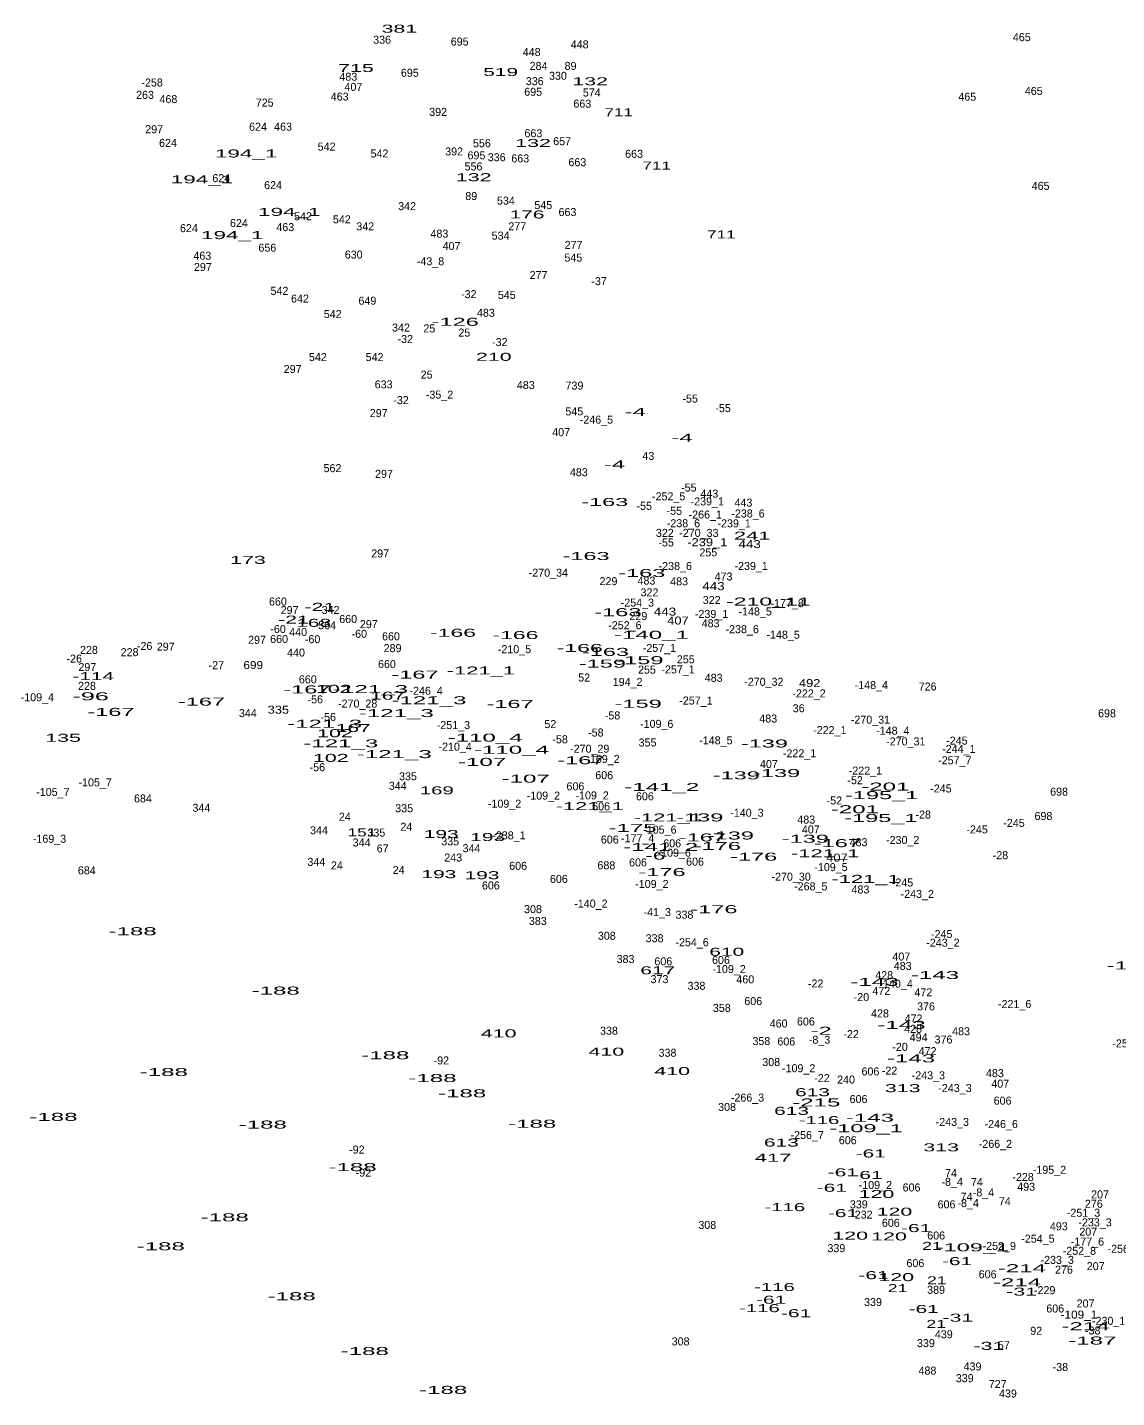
# Model space of a CAD drawing. Extents: x -658595 to -655205, y -1004347 to -1000147.
# Drawn here: x -656433 to -655888, y -1002919 to -1002234 of the extents above; entities that cross this region are included whole.
import ezdxf
from ezdxf.enums import TextEntityAlignment as Align

# ---------------------------------------------------------------- set-up
doc = ezdxf.new("R2010")
doc.units = 0
doc.header["$LTSCALE"] = 1.6
doc.layers.add('24', color=7, linetype='Continuous')

msp = doc.modelspace()

# ---------------------------------------------------------------- texts
at = {"layer": '24'}
for s, width, p in [('381', 2, (-656246.827, -1002236.84)), ('715', 2, (-656268.523, -1002256.5)), ('519', 1.95, (-656196.223, -1002258.51)), ('132', 2, (-656151.497, -1002263.15)), ('711', 1.6, (-656137.239, -1002278.62)), ('194_1', 2.1, (-656323.435, -1002299.23)), ('132', 2, (-656180.027, -1002293.97)), ('711', 1.6, (-656118.229, -1002305.26)), ('194_1', 2.1, (-656345.495, -1002312.17)), ('132', 2, (-656209.697, -1002311.09)), ('194_1', 2.1, (-656301.855, -1002328.43)), ('176', 1.95, (-656183.047, -1002329.73)), ('194_1', 2.1, (-656330.385, -1002340.03)), ('711', 1.6, (-656085.899, -1002339.69)), ('-126', 2.2, (-656218.915, -1002383.38)), ('210', 2, (-656199.664, -1002400.89)), ('-4', 2.25, (-656128.98, -1002428.43)), ('-4', 2.25, (-656105.59, -1002441.37)), ('-4', 2.25, (-656139.34, -1002454.68)), ('-163', 2.2, (-656144.225, -1002473.46)), ('241', 2.05, (-656070.523, -1002490.27)), ('-239_1', 1.2, (-656092.931, -1002493.55)), ('443', 1.25, (-656071.79, -1002494.51)), ('173', 2, (-656322.523, -1002502.4)), ('-163', 2.2, (-656153.545, -1002500.48)), ('-163', 2.2, (-656125.685, -1002508.95)), ('443', 1.25, (-656089.85, -1002515.51)), ('-210_11', 2.15, (-656062.46, -1002523.24)), ('-21', 2, (-656299.771, -1002532.26)), ('-21', 2, (-656286.561, -1002525.88)), ('-163', 2.2, (-656137.665, -1002528.54)), ('443', 1.25, (-656114.1, -1002528.25)), ('168', 1.95, (-656289.653, -1002533.87)), ('-166', 2.15, (-656220.039, -1002538.84)), ('407', 1.2, (-656107.61, -1002532.72)), ('-166', 2.15, (-656188.849, -1002539.98)), ('-140_1', 2.25, (-656120.869, -1002539.85)), ('-166', 2.15, (-656156.709, -1002546.45)), ('-163', 2.2, (-656143.845, -1002548.41)), ('-159', 2.2, (-656126.635, -1002552.54)), ('699', 1.1, (-656319.89, -1002554.98)), ('-121_1', 2.05, (-656206.134, -1002557.7)), ('-159', 2.2, (-656145.375, -1002554.26)), ('-114', 1.95, (-656399.862, -1002560.53)), ('-167', 2.2, (-656239.059, -1002559.75)), ('492', 1.2, (-656041.78, -1002563.99)), ('-96', 2.35, (-656401.153, -1002570.6)), ('-167', 2.2, (-656345.749, -1002573.25)), ('-167', 2.2, (-656293.069, -1002567.17)), ('102', 2, (-656279.644, -1002566.87)), ('-121_3', 2.25, (-656261.247, -1002567)), ('167', 1.95, (-656252.737, -1002570.28)), ('-121_3', 2.25, (-656232.067, -1002572.58)), ('-167', 2.2, (-656391.009, -1002578.39)), ('335', 1.2, (-656307.34, -1002577.29)), ('-121_3', 2.25, (-656248.357, -1002578.98)), ('-167', 2.2, (-656191.509, -1002574.4)), ('-159', 2.2, (-656127.485, -1002574.32)), ('-121_3', 2.25, (-656284.207, -1002584.3)), ('167', 1.95, (-656269.877, -1002586.43)), ('135', 2, (-656414.917, -1002591.35)), ('102', 2, (-656279.044, -1002589.04)), ('-110_4', 2.25, (-656203.979, -1002591.26)), ('-121_3', 2.25, (-656276.137, -1002594.11)), ('-121_3', 2.25, (-656249.367, -1002599.5)), ('-110_4', 2.25, (-656190.819, -1002597.31)), ('-139', 2.2, (-656064.425, -1002594.19)), ('102', 2, (-656281.144, -1002601.4)), ('-107', 2.25, (-656205.501, -1002603.4)), ('-167', 2.2, (-656156.139, -1002602.55)), ('-107', 2.25, (-656183.711, -1002611.76)), ('-139', 2.2, (-656078.455, -1002610.12)), ('-139', 2.2, (-656058.295, -1002608.97)), ('169', 1.9, (-656228.147, -1002617.62)), ('-141_2', 2.25, (-656115.693, -1002615.95)), ('-195_1', 2.2, (-656005.813, -1002620.01)), ('-201', 2.25, (-656003.957, -1002615.73)), ('-121_1', 2.05, (-656151.714, -1002625.5)), ('-201', 2.25, (-656019.167, -1002627.05)), ('-121_1', 2.05, (-656112.684, -1002631.17)), ('-139', 2.2, (-656096.705, -1002631.15)), ('-195_1', 2.2, (-656006.193, -1002631.43)), ('151', 1.6, (-656265.564, -1002638.61)), ('193', 1.95, (-656225.933, -1002639.44)), ('193', 1.95, (-656202.733, -1002640.96)), ('-175', 2.25, (-656130.315, -1002636.42)), ('-167', 2.2, (-656095.429, -1002641.15)), ('-139', 2.2, (-656081.405, -1002640.18)), ('-139', 2.2, (-656043.945, -1002641.8)), ('-141_2', 2.25, (-656116.273, -1002645.92)), ('-176', 2.2, (-656087.929, -1002645.44)), ('-167', 2.2, (-656027.919, -1002644.01)), ('-6', 2.1, (-656118.929, -1002650.25)), ('-176', 2.2, (-656069.769, -1002650.77)), ('-121_1', 2.05, (-656034.034, -1002649.08)), ('407', 1.2, (-656028.13, -1002651.24)), ('193', 1.95, (-656227.123, -1002659.51)), ('193', 1.95, (-656205.533, -1002660.03)), ('-176', 2.2, (-656115.599, -1002658.47)), ('-121_1', 2.05, (-656013.844, -1002661.87)), ('-176', 2.2, (-656089.639, -1002677.02)), ('-188', 2.25, (-656380.171, -1002688.04)), ('610', 1.95, (-656083.229, -1002698.31)), ('617', 1.95, (-656117.717, -1002707.6)), ('-143', 2.25, (-655979.146, -1002709.93)), ('-105_1', 2.25, (-655874.674, -1002705.17)), ('-143', 2.25, (-656009.386, -1002713.35)), ('-188', 2.25, (-656308.661, -1002717.72)), ('-143', 2.25, (-655995.886, -1002734.85)), ('410', 2, (-656197.219, -1002739.11)), ('-2', 2.2, (-656036.024, -1002737.79)), ('-188', 2.25, (-656253.881, -1002750.03)), ('410', 2, (-656143.399, -1002748.24)), ('410', 2, (-656110.499, -1002757.94)), ('-143', 2.25, (-655991.126, -1002751.59)), ('-188', 2.25, (-656364.571, -1002758.43)), ('-188', 2.25, (-656230.301, -1002761.44)), ('-188', 2.25, (-656215.471, -1002769.05)), ('613', 1.95, (-656040.363, -1002768.51)), ('313', 2, (-655995.287, -1002766.49)), ('613', 1.95, (-656050.833, -1002777.83)), ('-215', 2.25, (-656038.461, -1002773.65)), ('-188', 2.25, (-656419.731, -1002780.84)), ('-188', 2.25, (-656315.131, -1002784.69)), ('-188', 2.25, (-656180.471, -1002784.27)), ('-116', 1.9, (-656037.111, -1002782.44)), ('-143', 2.25, (-656011.666, -1002781.27)), ('-109_1', 2.2, (-656013.609, -1002786.52)), ('613', 1.95, (-656055.923, -1002793.67)), ('-61', 1.95, (-656011.255, -1002799.13)), ('313', 2, (-655976.077, -1002796.08)), ('-188', 2.25, (-656270.241, -1002805.96)), ('417', 2.05, (-656060.058, -1002801.28)), ('-61', 1.95, (-656025.225, -1002808.59)), ('-61', 1.95, (-656012.885, -1002809.89)), ('-61', 1.95, (-656030.695, -1002816.28)), ('120', 2, (-656008.404, -1002819.4)), ('-116', 1.9, (-656054.201, -1002825.95)), ('-188', 2.25, (-656334.141, -1002831.07)), ('-61', 1.95, (-656025.125, -1002828.95)), ('120', 2, (-655999.424, -1002828.24)), ('120', 2, (-656021.534, -1002840.22)), ('-61', 1.95, (-655988.555, -1002836.44)), ('-188', 2.25, (-656366.101, -1002845.53)), ('120', 2, (-656002.134, -1002840.61)), ('21', 1.65, (-655980.627, -1002845.34)), ('-109_1', 2.2, (-655960.419, -1002846.07)), ('-61', 1.95, (-655968.105, -1002852.96)), ('-61', 1.95, (-656009.865, -1002859.97)), ('120', 2, (-655998.514, -1002860.96)), ('-214', 2.25, (-655935.676, -1002856.49)), ('-116', 1.9, (-656059.381, -1002865.89)), ('21', 1.65, (-655997.837, -1002866.46)), ('21', 1.65, (-655978.247, -1002862.56)), ('-214', 2.25, (-655938.146, -1002863.53)), ('-188', 2.25, (-656300.671, -1002870.52)), ('-61', 1.95, (-656061.045, -1002872.26)), ('-31', 2, (-655935.841, -1002868.21)), ('-116', 1.9, (-656066.871, -1002876.46)), ('-61', 1.95, (-656048.555, -1002878.99)), ('-61', 1.95, (-655984.805, -1002876.88)), ('-31', 2, (-655967.701, -1002881.24)), ('-109_1', 1.1, (-655907.211, -1002879.69)), ('21', 1.65, (-655978.527, -1002884.34)), ('-214', 2.25, (-655903.906, -1002885.5)), ('-31', 2, (-655952.201, -1002895.32)), ('-187', 2.25, (-655900.515, -1002892.66)), ('-188', 2.25, (-656264.151, -1002897.91)), ('-188', 2.25, (-656224.981, -1002917.32))]:
    msp.add_text(s, height=4, dxfattribs=dict(at, width=width)).set_placement(p, align=Align.CENTER)
for s, p in [('336', (-656255.463, -1002242.35)), ('695', (-656216.688, -1002243.29)), ('465', (-655935.757, -1002241.09)), ('448', (-656180.716, -1002248.52)), ('448', (-656156.746, -1002244.69)), ('284', (-656177.281, -1002255.45)), ('89', (-656161.293, -1002255.45)), ('-258', (-656370.425, -1002263.76)), ('483', (-656272.361, -1002260.85)), ('695', (-656241.618, -1002258.89)), ('336', (-656179.193, -1002263.09)), ('330', (-656167.601, -1002260.39)), ('263', (-656373.983, -1002269.93)), ('463', (-656276.677, -1002270.8)), ('407', (-656269.811, -1002265.94)), ('695', (-656179.988, -1002268.4)), ('574', (-656150.687, -1002268.75)), ('465', (-655963.017, -1002270.86)), ('465', (-655929.797, -1002267.98)), ('468', (-656362.287, -1002272.06)), ('725', (-656314.163, -1002273.8)), ('392', (-656227.483, -1002278.44)), ('663', (-656155.418, -1002274.3)), ('297', (-656369.408, -1002287.1)), ('624', (-656317.507, -1002285.87)), ('463', (-656305.017, -1002285.83)), ('663', (-656179.858, -1002289.14)), ('624', (-656362.497, -1002293.95)), ('542', (-656283.211, -1002295.8)), ('542', (-656256.781, -1002299.23)), ('392', (-656219.493, -1002298.22)), ('556', (-656205.613, -1002294.12)), ('657', (-656165.528, -1002293.1)), ('556', (-656209.803, -1002305.72)), ('695', (-656208.328, -1002300.17)), ('336', (-656198.213, -1002301.11)), ('663', (-656186.418, -1002301.7)), ('663', (-656157.888, -1002303.6)), ('663', (-656129.548, -1002299.41)), ('624', (-656335.867, -1002311.58)), ('624', (-656309.977, -1002315.07)), ('465', (-655926.347, -1002315.42)), ('342', (-656242.991, -1002325.57)), ('89', (-656210.933, -1002320.51)), ('534', (-656193.601, -1002322.79)), ('545', (-656174.921, -1002325.04)), ('542', (-656295.001, -1002330.62)), ('542', (-656275.601, -1002332.14)), ('663', (-656162.838, -1002328.52)), ('624', (-656352.027, -1002336.57)), ('624', (-656327.047, -1002334)), ('463', (-656303.877, -1002336.06)), ('342', (-656263.911, -1002335.66)), ('483', (-656226.851, -1002339.32)), ('534', (-656196.261, -1002340.29)), ('277', (-656187.929, -1002335.62)), ('656', (-656312.828, -1002346.32)), ('407', (-656220.751, -1002345.47)), ('277', (-656159.789, -1002344.95)), ('463', (-656345.337, -1002350.33)), ('630', (-656269.687, -1002349.78)), ('-43_8', (-656231.277, -1002353.12)), ('545', (-656159.901, -1002351.29)), ('297', (-656345.068, -1002355.97)), ('277', (-656177.279, -1002359.98)), ('-37', (-656147.031, -1002363.06)), ('542', (-656306.791, -1002367.9)), ('642', (-656296.547, -1002371.78)), ('649', (-656262.823, -1002372.83)), ('-32', (-656212.155, -1002369.55)), ('545', (-656193.181, -1002369.94)), ('542', (-656280.161, -1002379.51)), ('483', (-656203.611, -1002378.88)), ('342', (-656246.031, -1002386.26)), ('25', (-656231.867, -1002386.68)), ('-32', (-656243.915, -1002392)), ('25', (-656214.377, -1002388.77)), ('-32', (-656196.655, -1002393.52)), ('542', (-656287.581, -1002401.01)), ('542', (-656259.241, -1002401.01)), ('297', (-656300.178, -1002406.96)), ('633', (-656254.723, -1002414.67)), ('25', (-656233.197, -1002409.79)), ('483', (-656183.651, -1002414.99)), ('739', (-656159.338, -1002415.26)), ('-32', (-656246.015, -1002422.53)), ('-35_2', (-656226.772, -1002419.78)), ('-55', (-656101.515, -1002421.76)), ('297', (-656257.198, -1002429.02)), ('545', (-656159.421, -1002428.16)), ('-55', (-656085.045, -1002426.53)), ('-246_5', (-656148.372, -1002432.29)), ('407', (-656165.981, -1002438.55)), ('562', (-656280.283, -1002456.55)), ('43', (-656122.401, -1002450.42)), ('297', (-656254.538, -1002459.4)), ('483', (-656157.151, -1002458.59)), ('-55', (-656102.185, -1002466.24)), ('443', (-656091.926, -1002469.3)), ('-55', (-656124.455, -1002475.38)), ('-252_5', (-656112.262, -1002470.64)), ('-239_1', (-656092.982, -1002473.17)), ('443', (-656074.896, -1002473.77)), ('-55', (-656109.435, -1002477.85)), ('-238_6', (-656104.878, -1002484.08)), ('-266_1', (-656093.957, -1002479.74)), ('-239_1', (-656079.532, -1002484.15)), ('-238_6', (-656072.618, -1002479.22)), ('322', (-656114.187, -1002488.91)), ('-270_33', (-656097.161, -1002488.91)), ('-55', (-656113.515, -1002493.68)), ('297', (-656256.438, -1002499.17)), ('255', (-656092.437, -1002498.65)), ('-270_34', (-656172.405, -1002508.81)), ('-238_6', (-656108.958, -1002505.47)), ('473', (-656084.837, -1002510.71)), ('-239_1', (-656071.032, -1002505.45)), ('229', (-656142.333, -1002513.04)), ('483', (-656123.361, -1002512.75)), ('483', (-656107.041, -1002513.14)), ('660', (-656307.542, -1002523.21)), ('-254_3', (-656127.917, -1002523.77)), ('322', (-656121.847, -1002518.65)), ('322', (-656090.747, -1002522.45)), ('-177_8', (-656053.057, -1002524.03)), ('297', (-656301.708, -1002527.51)), ('342', (-656281.221, -1002527.44)), ('660', (-656272.442, -1002531.96)), ('229', (-656127.403, -1002530.51)), ('-239_1', (-656090.812, -1002529.42)), ('-148_5', (-656069.03, -1002528.19)), ('-60', (-656307.494, -1002536.96)), ('440', (-656297.46, -1002538.46)), ('564', (-656282.967, -1002535.06)), ('297', (-656262.128, -1002534.53)), ('-252_6', (-656134.138, -1002535.06)), ('483', (-656091.291, -1002534.07)), ('-238_6', (-656075.498, -1002537.05)), ('-26', (-656374.16, -1002545.46)), ('297', (-656363.628, -1002545.78)), ('297', (-656317.988, -1002542.35)), ('660', (-656306.972, -1002541.95)), ('-60', (-656290.214, -1002542.05)), ('-60', (-656266.884, -1002539.36)), ('660', (-656251.052, -1002540.62)), ('-148_5', (-656055.06, -1002539.8)), ('-26', (-656409.34, -1002551.75)), ('228', (-656402.027, -1002547.4)), ('228', (-656381.677, -1002548.54)), ('440', (-656298.5, -1002548.73)), ('289', (-656250.253, -1002546.52)), ('-210_5', (-656189.31, -1002547.04)), ('-257_1', (-656116.872, -1002546.4)), ('255', (-656103.707, -1002552.12)), ('297', (-656402.808, -1002555.95)), ('-27', (-656338.331, -1002555.07)), ('660', (-656253.052, -1002554.51)), ('255', (-656123.097, -1002557.26)), ('-257_1', (-656107.562, -1002557.15)), ('228', (-656402.977, -1002565.38)), ('660', (-656292.612, -1002562.12)), ('52', (-656154.477, -1002561.2)), ('194_2', (-656132.768, -1002563.42)), ('483', (-656089.761, -1002561.35)), ('-270_32', (-656064.691, -1002563.35)), ('-148_4', (-656010.975, -1002564.98)), ('726', (-655982.818, -1002565.72)), ('-109_4', (-656427.78, -1002571.09)), ('-56', (-656288.89, -1002572.14)), ('-246_4', (-656233.476, -1002567.81)), ('-257_1', (-656098.632, -1002572.71)), ('-222_2', (-656042.102, -1002569.15)), ('344', (-656322.586, -1002579)), ('-270_28', (-656267.691, -1002574.23)), ('-58', (-656140.305, -1002580.17)), ('36', (-656047.283, -1002576.57)), ('698', (-655893.178, -1002579.08)), ('-56', (-656282.41, -1002580.98)), ('-251_3', (-656219.816, -1002584.98)), ('52', (-656171.407, -1002584.5)), ('-109_6', (-656118.231, -1002584.37)), ('483', (-656062.491, -1002581.71)), ('-270_31', (-656011.405, -1002582.28)), ('-58', (-656166.515, -1002592.07)), ('-58', (-656148.655, -1002588.71)), ('355', (-656122.807, -1002593.69)), ('-148_5', (-656088.65, -1002592.61)), ('-222_1', (-656031.716, -1002587.5)), ('-148_4', (-656000.235, -1002587.81)), ('-270_31', (-655993.735, -1002593.14)), ('-245', (-655968.189, -1002592.74)), ('-210_4', (-656218.974, -1002595.8)), ('-270_29', (-656151.716, -1002596.8)), ('-222_1', (-656046.836, -1002599.1)), ('-244_1', (-655967.245, -1002596.92)), ('-56', (-656287.84, -1002606.05)), ('-169_2', (-656145.077, -1002601.9)), ('407', (-656062.141, -1002604.45)), ('-257_7', (-655969.234, -1002602.59)), ('-105_7', (-656398.896, -1002613.62)), ('335', (-656242.557, -1002610.58)), ('606', (-656144.472, -1002610.03)), ('-52', (-656019.085, -1002612.53)), ('-222_1', (-656013.936, -1002607.76)), ('-105_7', (-656420.016, -1002618.42)), ('344', (-656247.656, -1002615.33)), ('-109_2', (-656174.886, -1002620.24)), ('606', (-656158.872, -1002615.6)), ('-109_2', (-656150.506, -1002620.14)), ('606', (-656124.132, -1002620.58)), ('-245', (-655976.179, -1002616.68)), ('698', (-655917.138, -1002618.27)), ('684', (-656375.027, -1002621.66)), ('344', (-656345.786, -1002626.34)), ('335', (-656244.457, -1002626.56)), ('-109_2', (-656194.276, -1002624.27)), ('606', (-656146.012, -1002625.59)), ('-52', (-656029.425, -1002622.67)), ('24', (-656274.101, -1002630.79)), ('-140_3', (-656073.144, -1002628.8)), ('483', (-656043.491, -1002632.22)), ('-28', (-655985.055, -1002629.7)), ('-245', (-655939.659, -1002633.9)), ('698', (-655924.938, -1002630.45)), ('-169_3', (-656421.727, -1002641.82)), ('344', (-656287.026, -1002637.57)), ('335', (-656258.347, -1002638.74)), ('24', (-656243.391, -1002635.83)), ('-238_1', (-656192.076, -1002640.1)), ('-177_4', (-656127.742, -1002641.54)), ('-105_6', (-656116.646, -1002637.24)), ('407', (-656041.231, -1002637.16)), ('-245', (-655958.109, -1002637.14)), ('344', (-656265.726, -1002643.68)), ('67', (-656255.198, -1002646.67)), ('335', (-656221.447, -1002643.11)), ('344', (-656210.796, -1002646.54)), ('606', (-656141.682, -1002642.21)), ('606', (-656110.502, -1002644.12)), ('483', (-656017.371, -1002643.55)), ('-230_2', (-655995.286, -1002642.44)), ('344', (-656288.356, -1002653.36)), ('24', (-656278.091, -1002655.14)), ('243', (-656219.951, -1002651.2)), ('606', (-656187.482, -1002655.36)), ('688', (-656143.383, -1002655.08)), ('606', (-656127.582, -1002653.63)), ('-109_6', (-656109.491, -1002648.78)), ('606', (-656099.072, -1002653.25)), ('-28', (-655946.445, -1002650.05)), ('684', (-656403.077, -1002657.62)), ('24', (-656247.191, -1002657.42)), ('606', (-656167.132, -1002661.89)), ('-270_30', (-656051.045, -1002660.78)), ('-109_5', (-656031.116, -1002656)), ('606', (-656201.122, -1002665.16)), ('-109_2', (-656120.646, -1002664.41)), ('-268_5', (-656041.238, -1002665.59)), ('483', (-656016.411, -1002667.18)), ('-245', (-655995.379, -1002663.68)), ('-140_2', (-656151.114, -1002674.21)), ('-243_2', (-655988.007, -1002669.39)), ('308', (-656180.071, -1002677)), ('383', (-656177.657, -1002682.91)), ('-41_3', (-656117.96, -1002678.47)), ('338', (-656104.357, -1002679.78)), ('-245', (-655975.789, -1002689.46)), ('308', (-656143.171, -1002690.32)), ('338', (-656119.287, -1002691.54)), ('-254_6', (-656100.552, -1002693.55)), ('-243_2', (-655975.167, -1002693.75)), ('383', (-656133.817, -1002701.93)), ('606', (-656114.912, -1002703.1)), ('606', (-656086.112, -1002702.43)), ('407', (-655995.961, -1002700.71)), ('-109_2', (-656082.056, -1002706.96)), ('428', (-656004.541, -1002710.02)), ('483', (-655995.291, -1002705.4)), ('373', (-656116.843, -1002711.98)), ('338', (-656098.367, -1002715.32)), ('460', (-656073.951, -1002712.1)), ('-22', (-656038.765, -1002714.17)), ('-140_4', (-655998.569, -1002714.31)), ('606', (-656069.982, -1002722.98)), ('-20', (-656015.929, -1002720.98)), ('472', (-656005.967, -1002717.9)), ('472', (-655984.967, -1002718.6)), ('358', (-656085.707, -1002726.37)), ('428', (-656006.631, -1002729.14)), ('376', (-655983.638, -1002725.62)), ('-221_6', (-655939.332, -1002724.44)), ('338', (-656142.117, -1002737.77)), ('460', (-656057.301, -1002734.16)), ('606', (-656043.672, -1002733.16)), ('428', (-655990.091, -1002736.85)), ('472', (-655989.867, -1002731.66)), ('358', (-656065.927, -1002742.93)), ('606', (-656053.462, -1002743.15)), ('-8_3', (-656036.843, -1002742.29)), ('-22', (-656021.075, -1002739.47)), ('494', (-655987.331, -1002741.09)), ('376', (-655974.888, -1002742.17)), ('483', (-655966.111, -1002738.05)), ('-252_7', (-655882.188, -1002744.12)), ('338', (-656112.827, -1002748.8)), ('-20', (-655996.619, -1002745.86)), ('472', (-655982.857, -1002747.98)), ('-92', (-656225.86, -1002752.64)), ('308', (-656061.011, -1002753.45)), ('-109_2', (-656047.286, -1002756.52)), ('606', (-656011.412, -1002758.13)), ('-22', (-656001.865, -1002757.74)), ('-22', (-656035.625, -1002761.45)), ('240', (-656023.595, -1002762.19)), ('-243_3', (-655982.467, -1002760.07)), ('483', (-655949.211, -1002758.99)), ('407', (-655946.511, -1002764.25)), ('-266_3', (-656072.843, -1002771.21)), ('606', (-656017.362, -1002771.96)), ('-243_3', (-655969.157, -1002766.45)), ('308', (-656083.081, -1002775.9)), ('606', (-655945.362, -1002772.73)), ('-243_3', (-655970.487, -1002783.38)), ('-246_6', (-655946.048, -1002784.43)), ('-256_7', (-656043.024, -1002789.91)), ('606', (-656022.742, -1002792.52)), ('-92', (-656268.1, -1002797.2)), ('-266_2', (-655948.953, -1002794.34)), ('-92', (-656264.83, -1002808.73)), ('74', (-655971.157, -1002808.93)), ('-228', (-655935.125, -1002810.9)), ('-195_2', (-655921.952, -1002807.29)), ('-109_2', (-656008.966, -1002814.9)), ('606', (-655990.872, -1002816.14)), ('-8_4', (-655970.568, -1002813.31)), ('74', (-655958.217, -1002813.4)), ('-8_4', (-655954.918, -1002818.6)), ('493', (-655933.577, -1002815.77)), ('207', (-655896.657, -1002819.61)), ('339', (-656017.223, -1002824.6)), ('606', (-655973.392, -1002824.59)), ('-8_4', (-655962.578, -1002823.96)), ('74', (-655963.357, -1002820.73)), ('74', (-655944.237, -1002823.01)), ('276', (-655899.748, -1002824.29)), ('232', (-656014.817, -1002829.71)), ('-251_3', (-655904.926, -1002828.78)), ('-233_3', (-655899.152, -1002833.59)), ('308', (-656092.961, -1002834.88)), ('606', (-656001.232, -1002833.81)), ('606', (-655978.572, -1002840.15)), ('493', (-655917.257, -1002835.55)), ('207', (-655902.557, -1002838.25)), ('339', (-656028.443, -1002846.48)), ('-252_9', (-655947.038, -1002845.38)), ('-254_5', (-655927.697, -1002841.74)), ('-177_6', (-655902.972, -1002843.2)), ('-256_8', (-655884.588, -1002846.8)), ('606', (-655988.942, -1002853.98)), ('-233_3', (-655918.072, -1002852.34)), ('-252_8', (-655906.982, -1002847.81)), ('606', (-655952.842, -1002859.55)), ('276', (-655914.688, -1002857.22)), ('207', (-655898.837, -1002855.48)), ('389', (-655978.613, -1002867.3)), ('-229', (-655924.31, -1002867.48)), ('339', (-656010.133, -1002873.42)), ('207', (-655903.877, -1002874.13)), ('606', (-655919.052, -1002876.65)), ('92', (-655928.573, -1002887.78)), ('-38', (-655900.305, -1002887.64)), ('-230_1', (-655892.37, -1002882.8)), ('308', (-656106.281, -1002893.1)), ('339', (-655983.693, -1002893.96)), ('439', (-655974.747, -1002889.54)), ('57', (-655944.743, -1002895.03)), ('488', (-655982.911, -1002907.67)), ('439', (-655960.387, -1002905.62)), ('-38', (-655916.475, -1002905.91)), ('339', (-655964.293, -1002911.47)), ('727', (-655947.799, -1002914.39)), ('439', (-655942.697, -1002919.13))]:
    msp.add_text(s, height=4, dxfattribs=at).set_placement(p, align=Align.CENTER)

doc.saveas('drawing.dxf')
